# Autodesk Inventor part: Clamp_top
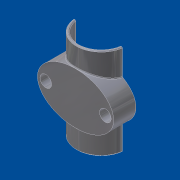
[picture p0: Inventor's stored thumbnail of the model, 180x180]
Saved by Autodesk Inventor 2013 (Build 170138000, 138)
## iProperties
Shininess: 64.0
Length Units: 11269
Angle Units: 11279
Time Units: 11290
Mass Units: 11283
Length Display Precision: 3
Angle Display Precision: 2
Compacted: True
Part Number: Clamp_top
Document SubType Name: Modeling
Created: 2002-10
Designer: roithn
Density: 1 g/cm^3
Material: Generic
Density: 0.0
Volumn: 0.0
Area: 0.0
PropertySet Name: Model Information
Control State: 0
Master: False
Checked Out: False
Author: roithn
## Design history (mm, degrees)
sketch "Sketch1" dims "d0" = 23, "d1" = 15.5
  geometry: 1 further point; 1 other entity
  constraints: 2 other
extrude "Extrusion1" new body sketch "Sketch1" distance "d2" = 15.5 (= d1); taper "d3" = 0 deg
sketch "Sketch2"
  geometry: L1 (-23, 15.5)-(23, 15.5) reference; L2 (-23, 0)-(23, 0) reference; L3 (15, 0)-(-15, 0); L4 (15, 0)-(-15, 0); C1 r 13.5 at (0, 0); A1 r 15 centre (0, 0) between (15, 0) and (-15, 0)
  constraints: 4 end point, 2 centre point, 2 point on circle, 2 point on line, 1 coincident, 1 collinear, 1 concentric, 1 midpoint
  dimensions: "d4" = 27 diameter of C1 (computed from d1); "d14" = 30 diameter of A1 (computed from d4)
extrude "Extrusion2" join sketch "Sketch2" stored distance "d5" = 55; taper "d6" = 0 deg
extrude "Extrusion3" cut sketch "Sketch2" stored distance "d7" = 55; taper "d8" = 0 deg
sketch "Sketch3"
  geometry: 4 further points; 1 other entity
  constraints: 1 horizontal alignment, 1 other
  dimensions: "d9" = 18 distance of point (18, 0) point (0, 0)
chamfer "Chamfer1" distance "d10" = 0.5; stored, may be unused: second distance "d11" = 2, angle "d25" = 45 deg
sketch "Sketch4"
  geometry: L1 (27.628, -32.233)-(-25.821, -32.233); L2 (-25.821, -32.233)-(-25.821, 31.553); L3 (-25.821, 31.553)-(27.628, 31.553); L4 (27.628, 31.553)-(27.628, -32.233)
  constraints: 8 end point, 2 parallel, 1 horizontal, 1 perpendicular
extrude "Extrusion4" cut sketch "Sketch4" distance "d12" = 2; taper "d13" = 0 deg
hole "Hole1" sketch "Sketch3" diameter "d15" = 7; stored, may be unused: countersink angle "d19" = 82 deg, drill point angle "d21" = 118 deg; dims "d16" = 6, "d17" = 4, "d18" = 2, "d20" = 8
mirror "Mirror1"
fillet "Fillet1" dims "d22" = 0.5
body "Solid1"
